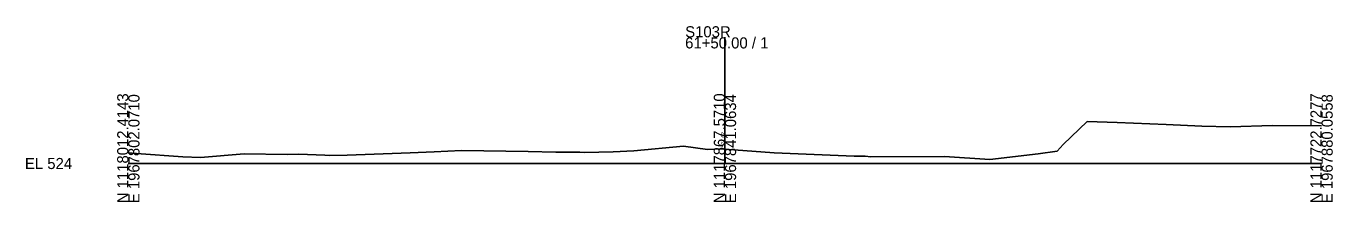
# Model space of a CAD drawing. Extents: x 974 to 1303, y 990 to 10019.
# Drawn here: x 974.3 to 1302.8, y 3990.3 to 4034.7 of the extents above; entities that cross this region are included whole.
import ezdxf

# ---------------------------------------------------------------- set-up
doc = ezdxf.new("R2010")
doc.units = 0
for name, color, linetype in [('Level 10', 7, 'Continuous'), ('Level 60', 7, 'Continuous'), ('Level 63', 7, 'Continuous')]:
    doc.layers.add(name, color=color, linetype=linetype)

msp = doc.modelspace()

# ---------------------------------------------------------------- linework, layer by layer
at = {"layer": 'Level 60'}
for p, q in [((1235.06, 4004.82), (1241.06, 4010.61)), ((1241.06, 4010.61), (1248.63, 4010.32)), ((1248.63, 4010.32), (1260.97, 4009.81)), ((1260.97, 4009.81), (1269.92, 4009.44)), ((1269.92, 4009.44), (1276.98, 4009.21)), ((1276.98, 4009.21), (1287.65, 4009.59)), ((1287.65, 4009.59), (1300, 4009.46)), ((1233.54, 4003.1), (1235.06, 4004.82)), ((1000, 4002.69), (1002.07, 4002.51)), ((1002.07, 4002.51), (1013.68, 4001.69)), ((1013.68, 4001.69), (1018.16, 4001.55)), ((1018.16, 4001.55), (1029.15, 4002.44)), ((1029.15, 4002.44), (1039.96, 4002.23)), ((1039.96, 4002.23), (1042.84, 4002.32)), ((1042.84, 4002.32), (1049.42, 4002.07)), ((1049.42, 4002.07), (1050.47, 4002.05)), ((1050.47, 4002.05), (1055.04, 4002.14)), ((1055.04, 4002.14), (1070.89, 4002.73)), ((1070.89, 4002.73), (1076.89, 4002.98)), ((1076.89, 4002.98), (1083.74, 4003.25)), ((1083.74, 4003.25), (1100.49, 4003.07)), ((1100.49, 4003.07), (1107.51, 4002.82)), ((1107.51, 4002.82), (1113.5, 4002.84)), ((1113.5, 4002.84), (1114.69, 4002.8)), ((1114.69, 4002.8), (1121.87, 4002.91)), ((1121.87, 4002.91), (1127.08, 4003.18)), ((1127.08, 4003.18), (1139.55, 4004.34)), ((1139.55, 4004.34), (1145.64, 4003.55)), ((1145.64, 4003.55), (1149.1, 4003.69)), ((1149.1, 4003.69), (1150, 4003.62)), ((1150, 4003.62), (1162.34, 4002.67)), ((1162.34, 4002.67), (1182.49, 4001.89)), ((1182.49, 4001.89), (1184.68, 4001.88)), ((1184.68, 4001.88), (1185.28, 4001.88)), ((1185.28, 4001.88), (1186.68, 4001.72)), ((1186.68, 4001.72), (1205.23, 4001.8)), ((1205.23, 4001.8), (1216.63, 4000.98)), ((1216.63, 4000.98), (1228.76, 4002.44)), ((1228.76, 4002.44), (1233.54, 4003.1))]:
    msp.add_line(p, q, dxfattribs=at)
at = {"layer": 'Level 63'}
for p, q in [((1150, 4000), (1150, 4031.82)), ((1000, 4000), (1150, 4000)), ((1150, 4000), (1300, 4000))]:
    msp.add_line(p, q, dxfattribs=at)

# ---------------------------------------------------------------- texts
at = {"layer": 'Level 10'}
msp.add_text('527.62', height=0.9, rotation=90, dxfattribs=at).set_placement((1149.95, 4004.12))
at = {"layer": 'Level 63'}
for s, p in [('S103R', (1140, 4031.82)), ('61+50.00 / 1', (1140, 4029.02)), ('EL 524', (974, 3998.6))]:
    msp.add_text(s, height=2.8, dxfattribs=at).set_placement(p)
for s, p in [('N 1118012.4143', (1000, 3990)), ('E 1967802.0710', (1002.8, 3990)), ('N 1117867.5710', (1150, 3990)), ('E 1967841.0634', (1152.8, 3990)), ('N 1117722.7277', (1300, 3990)), ('E 1967880.0558', (1302.8, 3990))]:
    msp.add_text(s, height=2.8, rotation=90, dxfattribs=at).set_placement(p)

doc.saveas('drawing.dxf')
